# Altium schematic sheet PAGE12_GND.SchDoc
size 381 x 304 mm; SheetNumber: 13; SheetTotal: 28
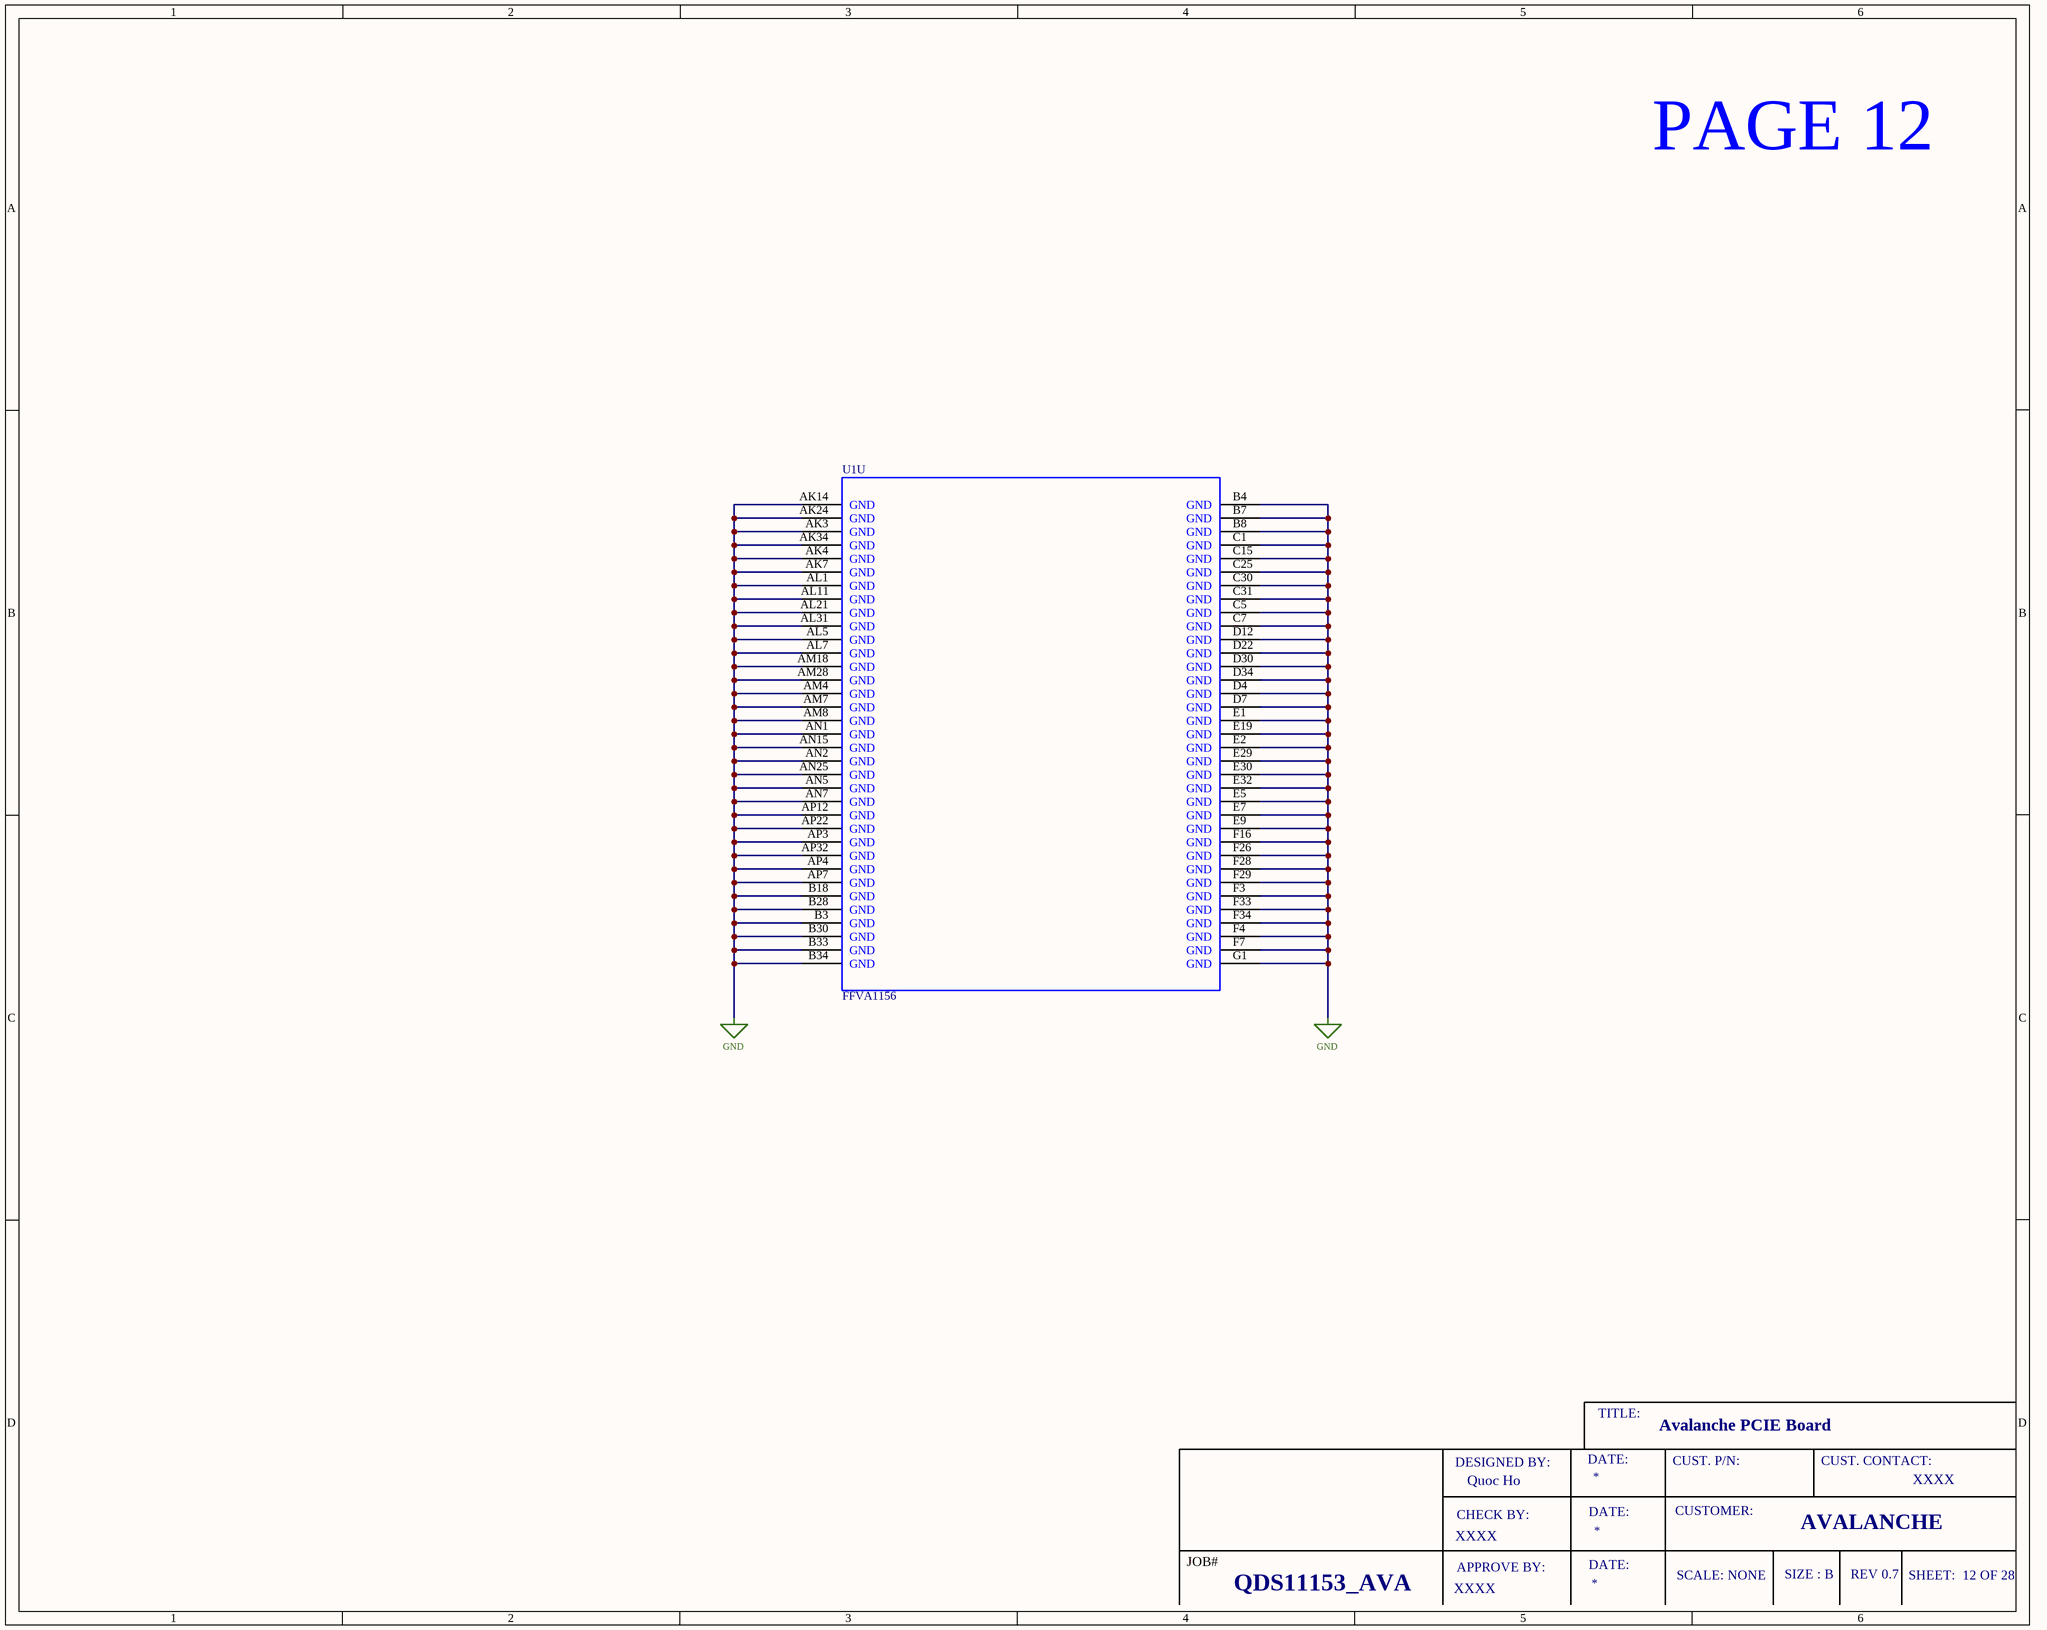
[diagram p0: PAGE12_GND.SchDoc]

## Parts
U1  FFVA1156  [FFVA1156]  (part U of 25)

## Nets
GND: U1.AK3(GND) U1.AK4(GND) U1.AK7(GND) U1.AK14(GND) U1.AK24(GND) U1.AK34(GND) U1.AL1(GND) U1.AL5(GND) U1.AL7(GND) U1.AL11(GND) U1.AL21(GND) U1.AL31(GND) U1.AM4(GND) U1.AM7(GND) U1.AM8(GND) U1.AM18(GND) U1.AM28(GND) U1.AN1(GND) U1.AN2(GND) U1.AN5(GND) U1.AN7(GND) U1.AN15(GND) U1.AN25(GND) U1.AP3(GND) U1.AP4(GND) U1.AP7(GND) U1.AP12(GND) U1.AP22(GND) U1.AP32(GND) U1.B3(GND) U1.B4(GND) U1.B7(GND) U1.B8(GND) U1.B18(GND) U1.B28(GND) U1.B30(GND) U1.B33(GND) U1.B34(GND) U1.C1(GND) U1.C5(GND) U1.C7(GND) U1.C15(GND) U1.C25(GND) U1.C30(GND) U1.C31(GND) U1.D4(GND) U1.D7(GND) U1.D12(GND) U1.D22(GND) U1.D30(GND) U1.D34(GND) U1.E1(GND) U1.E2(GND) U1.E5(GND) U1.E7(GND) U1.E9(GND) U1.E19(GND) U1.E29(GND) U1.E30(GND) U1.E32(GND) U1.F3(GND) U1.F4(GND) U1.F7(GND) U1.F16(GND) U1.F26(GND) U1.F28(GND) U1.F29(GND) U1.F33(GND) U1.F34(GND) U1.G1(GND)

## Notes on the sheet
- PAGE 12
- TITLE:
- Avalanche PCIE Board
- DESIGNED BY:
- CHECK BY:
- Quoc Ho
- DATE:
- CUST. P/N:
- CUSTOMER:
- CUST. CONTACT:
- XXXX
- JOB#
- APPROVE BY:
- SCALE: NONE
- SIZE : B
- AVALANCHE
- REV 0.7
- SHEET:  12 OF 28
- QDS11153_AVA

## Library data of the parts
U1 = FFVA1156: IC FPGA 516 I/O 1156FCBGA; Manufacturer Part Number: XCKU15P-1FFVA1156E; Manufacturer: AMD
